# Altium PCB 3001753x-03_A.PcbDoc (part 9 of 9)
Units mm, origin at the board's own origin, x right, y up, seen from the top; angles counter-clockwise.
Board outline 210 x 130 mm, 8 copper layers (1-TOP, 2-GND, 3-INTOP, 4-PWR, 5-PWR, 6-INBOT, 7-GND, 8-BOTTOM), stack 1.646 mm thick; 676 components, 623 nets, 2861 pads, 2382 vias.
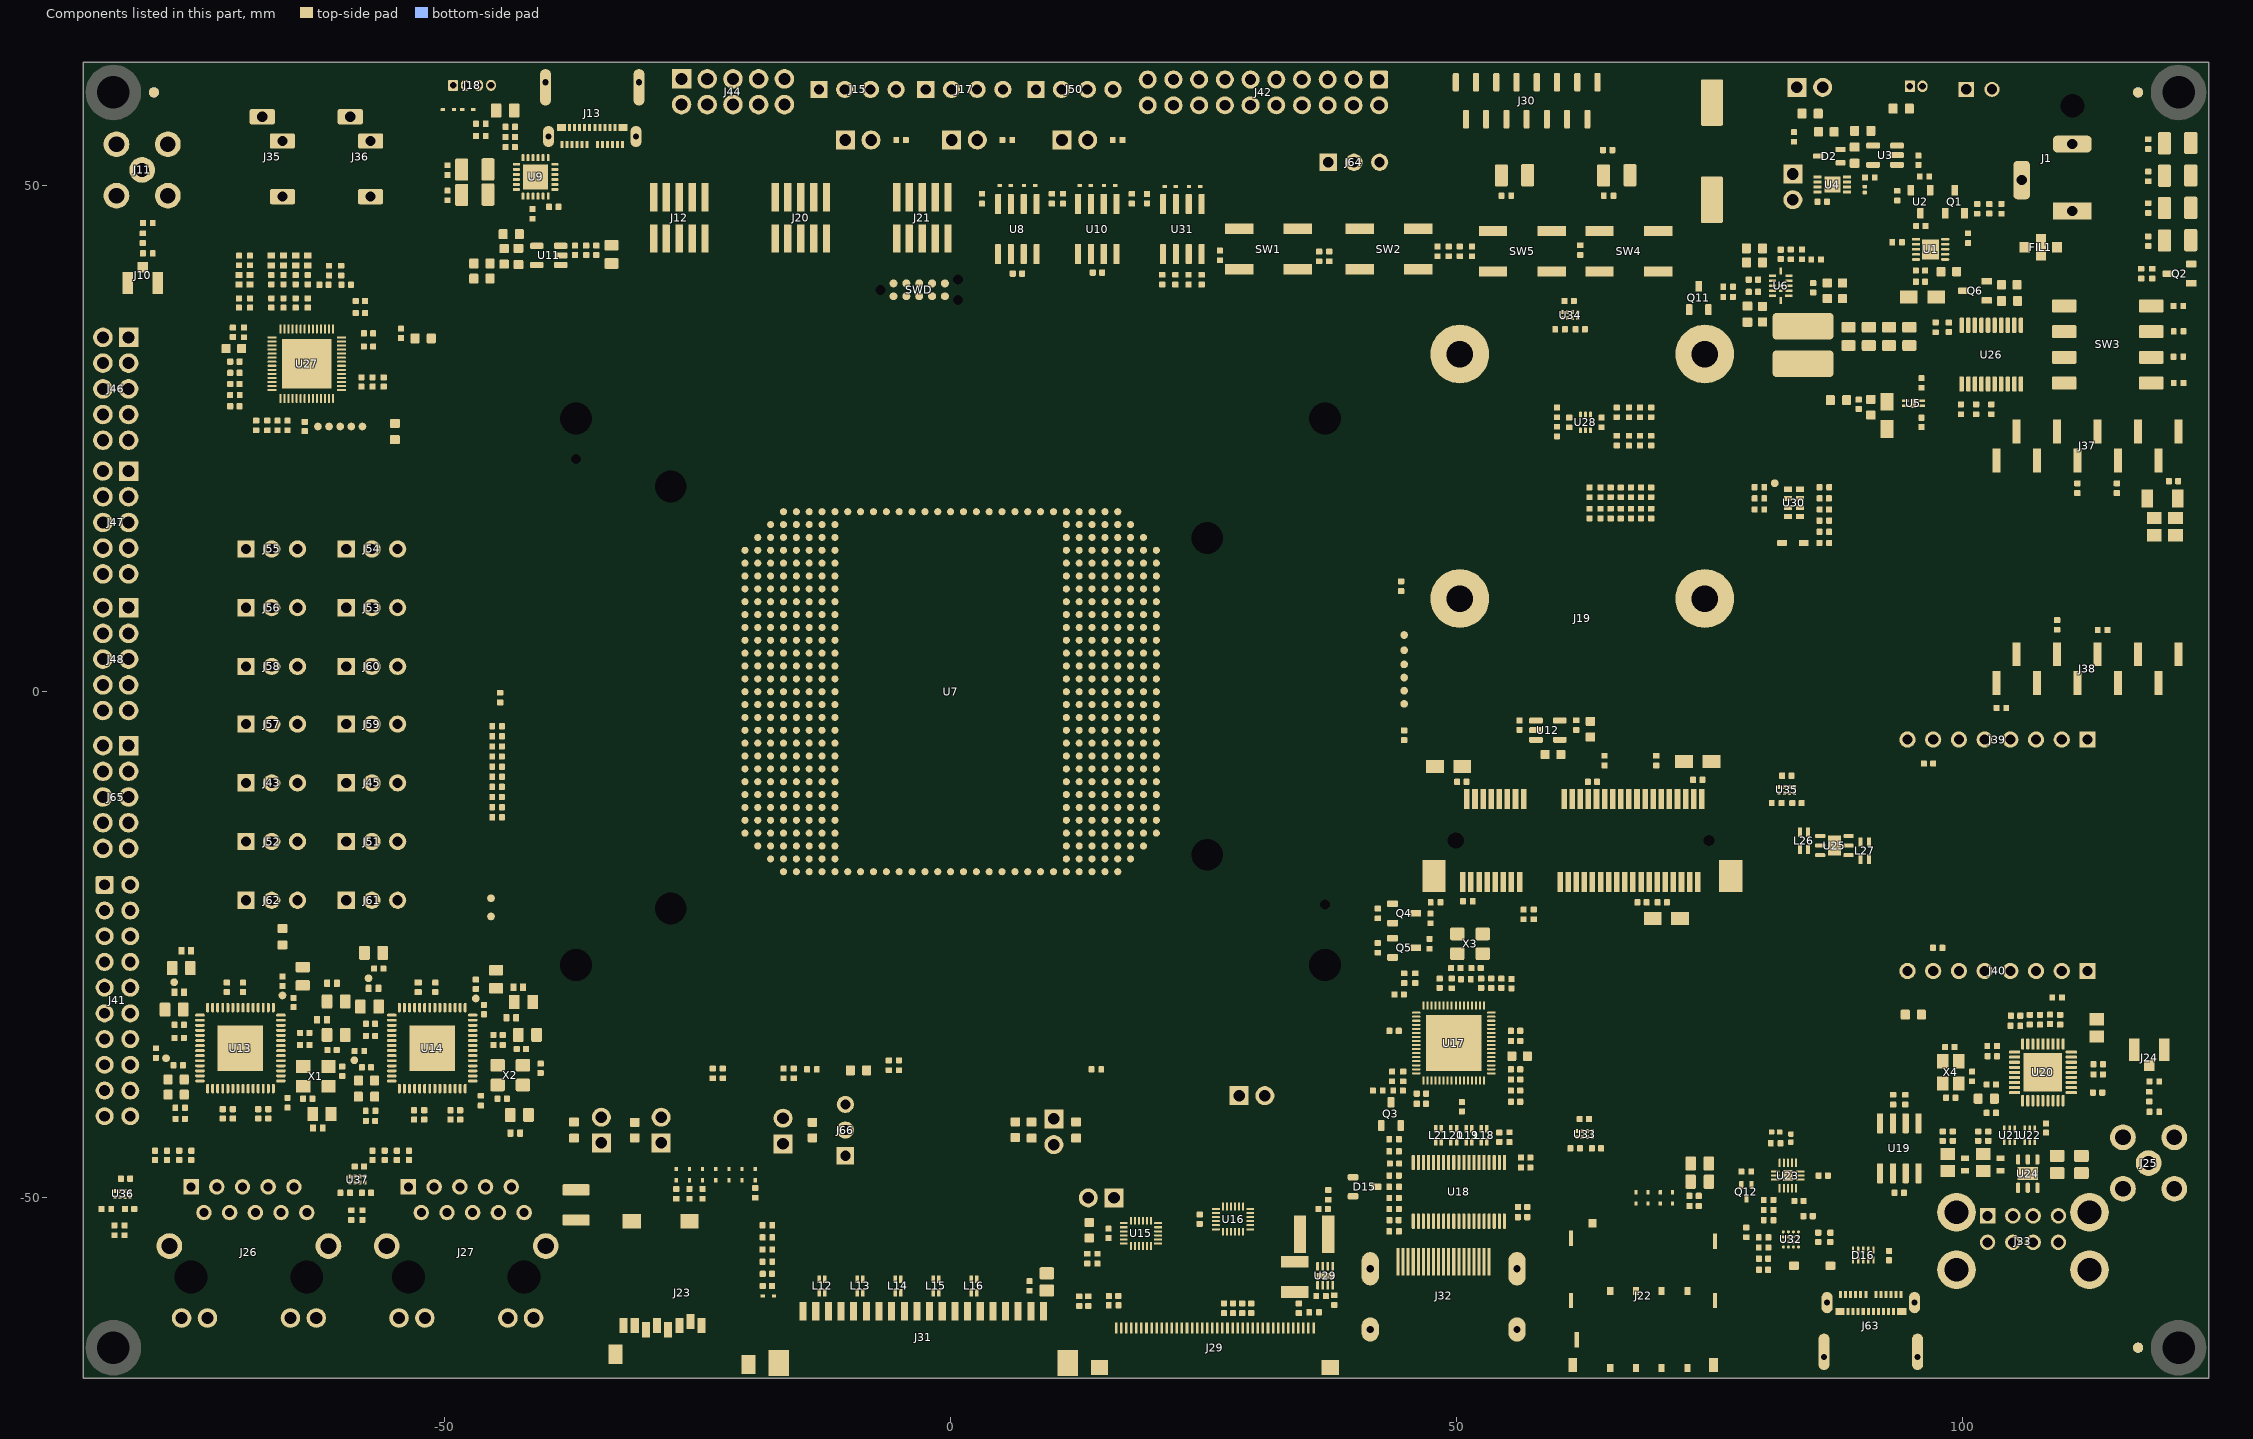
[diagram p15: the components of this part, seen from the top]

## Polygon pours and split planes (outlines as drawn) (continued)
3V3_ETH1 on 5-PWR (split plane): -59.451,-44.337 -61.563,-46.449 -77.2,-46.449 -77.239,-46.454 -77.276,-46.469 -77.307,-46.493 -80.707,-49.893 -80.731,-49.924 -80.746,-49.961 -80.751,-50 -80.751,-52.037 -81.363,-52.649 -82.837,-52.649 -83.149,-52.337 -83.149,-47.563 -79.193,-43.607 -79.169,-43.576 -79.154,-43.539 -79.149,-43.5 -79.149,-41.6 -79.149,-26.463 -76.837,-24.151 -59.451,-24.151
3V3_ETH2 on 5-PWR (split plane): -33.151,-33.163 -33.151,-42.437 -33.863,-43.149 -38.7,-43.149 -38.739,-43.154 -38.776,-43.169 -38.807,-43.193 -39.707,-44.093 -39.731,-44.124 -39.746,-44.161 -39.751,-44.2 -39.751,-46.537 -39.763,-46.549 -53.5,-46.549 -53.539,-46.554 -53.576,-46.569 -53.607,-46.593 -57.913,-50.899 -59.187,-50.899 -59.649,-50.437 -59.649,-48.3 -59.654,-48.261 -59.663,-48.239 -59.669,-48.224 -59.693,-48.193 -61.286,-46.6 -59.193,-44.507 -59.169,-44.476 -59.154,-44.439 -59.149,-44.4 -59.149,-24.251 -42.063,-24.251
1V8_SOM_EXT on 5-PWR (split plane): 270 vertices, not listed, extent -85.198,-67.298 87.449,57.249
NetC72_2 on 5-PWR (split plane): -64.551,-33.763 -64.551,-38.437 -67.063,-40.949 -73.237,-40.949 -75.749,-38.437 -75.749,-35.5 -75.749,-33.263 -74.937,-32.451 -65.863,-32.451
NetC99_2 on 5-PWR (split plane): -45.451,-33.763 -45.451,-38.237 -48.363,-41.149 -54.537,-41.149 -57.049,-38.637 -57.049,-35.7 -57.049,-33.063 -56.237,-32.251 -46.963,-32.251
VCC_MCA on 5-PWR (split plane): 84.749,61.698 84.749,57 84.749,55.5 84.754,55.461 84.769,55.424 84.793,55.393 86.693,53.493 86.724,53.469 86.761,53.454 86.8,53.449 87.637,53.449 89.649,51.437 89.649,48.463 88.693,47.507 82.537,41.351 24,41.351 23.961,41.346 23.924,41.331 23.893,41.307 21.293,38.707 21.269,38.676 21.263,38.661 21.254,38.639 21.249,38.6 21.249,7.493 20.892,7.136 19.748,7.136 18.566,8.318 18.566,35.2 18.561,35.239 18.546,35.276 18.522,35.307 18.491,35.331 18.477,35.336 16.607,37.207 16.576,37.231 16.539,37.246 16.5,37.251 -20.137,37.251 -21.149,38.263 -21.149,41.037 -20.037,42.149 -10.3,42.149 -10.261,42.154 -10.239,42.163 -10.224,42.169 -10.193,42.193 -9.093,43.293 -9.069,43.324 -9.054,43.361 -9.049,43.4 -9.049,48.8 -9.054,48.839 -9.069,48.876 -9.093,48.907 -9.593,49.407 -9.624,49.431 -9.661,49.446 -9.7,49.451 -21.037,49.451 -23.793,52.207 -29.093,57.507 -29.124,57.531 -29.161,57.546 -29.2,57.551 -74,57.551 -74.039,57.546 -74.061,57.537 -74.076,57.531 -74.107,57.507 -77.407,54.207 -77.431,54.176 -77.446,54.139 -77.451,54.1 -77.451,16.363 -79.463,14.351 -85.198,14.351 -85.198,61.698
USBC_VBUS on 5-PWR (split plane): 95.371,-55.554 95.371,-67.298 86.41,-67.298 86.41,-59.78 86.4,-59.731 86.372,-59.689 85.029,-58.346 85.029,-55.254 85.954,-54.329 94.146,-54.329
5V on 5-PWR (split plane): 87.449,-22.8 87.454,-22.839 87.469,-22.876 87.493,-22.907 88.193,-23.607 88.224,-23.631 88.261,-23.646 88.3,-23.651 97.337,-23.651 97.649,-23.963 97.649,-25.537 97.337,-25.849 88.1,-25.849 88.061,-25.854 88.039,-25.863 88.024,-25.869 87.993,-25.893 87.643,-26.243 87.642,-26.245 87.64,-26.246 64.142,-51.095 56.687,-58.549 9.663,-58.549 8.651,-57.537 8.651,-55.463 11.563,-52.551 20.425,-52.551 20.464,-52.546 20.486,-52.537 20.501,-52.531 20.532,-52.507 23.388,-49.651 35.575,-49.651 35.614,-49.646 35.636,-49.637 35.651,-49.631 35.682,-49.607 37.238,-48.051 51.7,-48.051 51.739,-48.046 51.761,-48.037 51.776,-48.031 51.807,-48.007 82.607,-17.207 82.631,-17.176 82.646,-17.139 82.651,-17.1 82.651,29.037 84.063,30.449 87.449,30.449
VIN_PROT on 5-PWR (split plane): 123.798,61.698 123.798,-67.298 95.629,-67.298 95.629,-55.5 95.62,-55.45 95.592,-55.408 94.292,-54.108 94.25,-54.08 94.2,-54.071 85.9,-54.071 85.85,-54.08 85.808,-54.108 84.808,-55.108 84.78,-55.15 84.771,-55.2 84.771,-58.4 84.78,-58.45 84.808,-58.492 86.151,-59.834 86.151,-67.298 3.451,-67.298 3.451,-43.851 8.9,-43.851 8.939,-43.846 8.976,-43.831 9.007,-43.807 9.031,-43.776 9.046,-43.739 9.051,-43.7 9.051,-41.263 10.5,-39.814 11.949,-41.263 11.949,-50.437 11.493,-50.893 11.469,-50.924 11.454,-50.961 11.449,-51 11.449,-52.259 11.424,-52.269 11.393,-52.293 8.393,-55.293 8.369,-55.324 8.354,-55.361 8.349,-55.4 8.349,-57.6 8.354,-57.639 8.369,-57.676 8.393,-57.707 9.493,-58.807 9.524,-58.831 9.561,-58.846 9.6,-58.851 56.75,-58.851 56.789,-58.846 56.826,-58.831 56.857,-58.807 64.357,-51.307 64.358,-51.305 64.36,-51.304 87.858,-26.455 88.163,-26.151 97.4,-26.151 97.439,-26.146 97.476,-26.131 97.507,-26.107 97.907,-25.707 97.931,-25.676 97.946,-25.639 97.951,-25.6 97.951,-23.9 97.946,-23.861 97.931,-23.824 97.907,-23.793 97.507,-23.393 97.476,-23.369 97.439,-23.354 97.4,-23.349 88.363,-23.349 87.751,-22.737 87.751,30.6 87.751,36.2 87.746,36.239 87.731,36.276 87.707,36.307 82.814,41.2 88.907,47.293 89.907,48.293 89.931,48.324 89.946,48.361 89.951,48.4 89.951,51.5 89.946,51.539 89.931,51.576 89.907,51.607 87.807,53.707 87.776,53.731 87.739,53.746 87.7,53.751 86.863,53.751 85.051,55.563 85.051,57 85.051,61.698
5V_DBG on 5-PWR (split plane): -31.251,57.237 -31.251,44.963 -32.163,44.051 -38.337,44.051 -39.569,45.283 -39.569,57.249 -31.263,57.249
VSYS2 on 5-PWR (split plane): 17.649,-26.237 17.37,-26.516 7.093,-36.793 7.069,-36.824 7.063,-36.839 7.054,-36.861 7.049,-36.9 7.049,-43.549 3.451,-43.549 3.451,-30.863 15.307,-19.007 15.331,-18.976 15.346,-18.939 15.351,-18.9 15.351,-14.663 15.963,-14.051 17.649,-14.051
VSYS on 5-PWR (split plane): 21.749,-10.363 21.749,-28.1 21.749,-28.137 10.393,-39.493 8.793,-41.093 8.769,-41.124 8.754,-41.161 8.749,-41.2 8.749,-43.549 7.351,-43.549 7.351,-36.963 17.584,-26.73 17.907,-26.407 17.931,-26.376 17.946,-26.339 17.951,-26.3 17.951,-9.063 18.063,-8.951 20.337,-8.951
1V8_PHY_1 on 4-PWR (split plane): -75.407,-24.807 -74.551,-25.663 -74.551,-27.5 -74.546,-27.539 -74.537,-27.561 -74.531,-27.576 -74.507,-27.607 -73.907,-28.207 -73.876,-28.231 -73.839,-28.246 -73.8,-28.251 -64.263,-28.251 -63.507,-29.007 -62.751,-29.763 -62.751,-36.1 -62.751,-39.437 -63.763,-40.449 -74,-40.449 -74.039,-40.454 -74.065,-40.465 -74.076,-40.469 -74.107,-40.493 -75.107,-41.493 -81.663,-48.049 -81.837,-48.049 -82.349,-47.537 -82.349,-47.363 -79.093,-44.107 -79.069,-44.076 -79.063,-44.061 -79.054,-44.039 -79.049,-44 -79.049,-40.4 -79.049,-39.7 -79.049,-28.7 -79.049,-26.263 -77.237,-24.451 -75.763,-24.451
3V3_SOM_EXT on 4-PWR (split plane): 198 vertices, not listed, extent -85.198,-67.298 123.798,61.698
3V3 on 4-PWR (split plane): -31.251,61.698 -31.251,42.6 -31.246,42.561 -31.237,42.539 -31.231,42.524 -31.207,42.493 -25.607,36.893 -18.607,29.893 -18.576,29.869 -18.539,29.854 -18.5,29.849 39.2,29.849 39.239,29.854 39.276,29.869 39.307,29.893 46.263,36.849 49.337,36.849 50.149,36.037 50.149,9.263 34.093,-6.793 34.069,-6.824 34.054,-6.861 34.049,-6.9 34.049,-22.137 13.037,-43.149 -2.2,-43.149 -6.049,-43.149 -6.049,-38.563 0.463,-32.051 3.8,-32.051 3.839,-32.046 3.876,-32.031 3.907,-32.007 15.407,-20.507 15.431,-20.476 15.437,-20.461 15.446,-20.439 15.451,-20.4 15.451,-15.6 15.446,-15.561 15.431,-15.524 15.407,-15.493 15.007,-15.093 14.976,-15.069 14.961,-15.063 14.939,-15.054 14.9,-15.049 13.2,-15.049 13.161,-15.054 13.139,-15.063 13.124,-15.069 13.093,-15.093 12.593,-15.593 12.569,-15.624 12.563,-15.639 12.554,-15.661 12.549,-15.7 12.549,-18.637 6.237,-24.949 -3.9,-24.949 -3.939,-24.954 -3.976,-24.969 -4.007,-24.993 -18.307,-39.293 -18.331,-39.324 -18.346,-39.361 -18.351,-39.4 -18.351,-43.149 -32.537,-43.149 -32.849,-42.837 -32.849,-42 -32.849,-27.5 -32.854,-27.461 -32.869,-27.424 -32.893,-27.393 -36.349,-23.937 -36.349,28.5 -36.354,28.539 -36.369,28.576 -36.393,28.607 -46.249,38.463 -46.249,39 -46.249,40.137 -40.893,45.493 -40.869,45.524 -40.854,45.561 -40.849,45.6 -40.849,55.7 -40.854,55.739 -40.869,55.776 -40.893,55.807 -41.893,56.807 -41.924,56.831 -41.939,56.837 -41.961,56.846 -42,56.851 -43.7,56.851 -43.739,56.846 -43.776,56.831 -43.807,56.807 -44.663,55.951 -72.9,55.951 -72.939,55.946 -72.976,55.931 -73.007,55.907 -75.207,53.707 -75.231,53.676 -75.237,53.661 -75.246,53.639 -75.251,53.6 -75.251,-4.137 -77.563,-6.449 -85.198,-6.449 -85.198,61.698
3V3_CODEC on 4-PWR (split plane): -52.751,30.037 -52.751,26.563 -53.363,25.951 -68.737,25.951 -70.249,27.463 -70.249,28.5 -70.249,31.437 -69.537,32.149 -54.863,32.149
1V8_PHY_2 on 4-PWR (split plane): -44.557,-29.007 -43.551,-30.013 -43.551,-35.85 -43.551,-39.187 -44.913,-40.549 -53.5,-40.549 -53.539,-40.554 -53.576,-40.569 -53.607,-40.593 -55.963,-42.949 -58.537,-42.949 -59.949,-41.537 -59.949,-40 -59.949,-30.513 -58.443,-29.007 -57.087,-27.651 -45.913,-27.651
3V3_DBG on 4-PWR (split plane): -41.151,55.637 -41.151,45.663 -46.507,40.307 -46.531,40.276 -46.546,40.239 -46.551,40.2 -46.551,39.151 -50.249,39.151 -50.249,55.649 -44.6,55.649 -44.561,55.654 -44.524,55.669 -44.493,55.693 -43.637,56.549 -42.063,56.549
1V8 on 4-PWR (split plane): 15.149,-15.663 15.149,-20.337 3.737,-31.749 0.4,-31.749 0.361,-31.754 0.339,-31.763 0.324,-31.769 0.293,-31.793 -6.307,-38.393 -6.331,-38.424 -6.346,-38.461 -6.351,-38.5 -6.351,-43.149 -18.049,-43.149 -18.049,-39.463 -3.837,-25.251 6.3,-25.251 6.339,-25.246 6.361,-25.237 6.376,-25.231 6.407,-25.207 12.807,-18.807 12.831,-18.776 12.837,-18.761 12.846,-18.739 12.851,-18.7 12.851,-15.763 13.263,-15.351 14.837,-15.351
5V_OUT_HDMI on 4-PWR (split plane): 56.349,-49.863 56.349,-54.837 55.437,-55.749 43.163,-55.749 42.151,-54.737 42.151,-49.563 42.663,-49.051 55.537,-49.051
NetC148_2 on 4-PWR (split plane): 115.349,-33.963 115.349,-40.537 113.637,-42.249 105.563,-42.249 103.551,-40.237 103.551,-36.063 104.063,-35.551 106,-35.551 106.039,-35.546 106.061,-35.537 106.076,-35.531 106.107,-35.507 106.507,-35.107 106.531,-35.076 106.535,-35.065 106.546,-35.039 106.551,-35 106.551,-34.063 107.363,-33.251 114.637,-33.251
VIN on 4-PWR (split plane): 105.549,43.377 105.549,41.763 105.337,41.551 101.363,41.551 98.507,44.407 98.476,44.431 98.439,44.446 98.4,44.451 92.863,44.451 91.851,45.463 91.851,51.537 92.163,51.849 97.077,51.849
5V on 4-PWR (split plane): 6.549,61.698 6.549,50.9 6.554,50.861 6.569,50.824 6.593,50.793 10.243,47.143 10.893,46.493 10.924,46.469 10.935,46.465 10.961,46.454 11,46.449 18.437,46.449 19.149,45.737 19.149,40.1 19.154,40.061 19.169,40.024 19.193,39.993 19.593,39.593 19.624,39.569 19.661,39.554 19.7,39.549 20.4,39.549 20.439,39.554 20.476,39.569 20.507,39.593 20.907,39.993 20.931,40.024 20.946,40.061 20.951,40.1 20.951,45.737 21.663,46.449 75.737,46.449 76.649,45.537 76.649,43 76.649,42.7 76.649,41.2 76.654,41.161 76.663,41.139 76.669,41.124 76.693,41.093 87.449,30.337 87.449,26.651 81.413,26.651 71.857,36.207 71.826,36.231 71.811,36.237 71.789,36.246 71.75,36.251 50.363,36.251 49.507,37.107 49.476,37.131 49.439,37.146 49.4,37.151 46.2,37.151 46.161,37.146 46.124,37.131 46.093,37.107 39.137,30.151 -18.437,30.151 -25.393,37.107 -30.949,42.663 -30.949,61.698
3V3_USB on 4-PWR (split plane): 115.449,-30.563 115.449,-32.137 114.637,-32.949 107.3,-32.949 107.261,-32.954 107.235,-32.965 107.224,-32.969 107.193,-32.993 106.293,-33.893 106.269,-33.924 106.263,-33.939 106.254,-33.961 106.249,-34 106.249,-34.937 105.937,-35.249 104,-35.249 103.961,-35.254 103.939,-35.263 103.924,-35.269 103.893,-35.293 103.293,-35.893 103.269,-35.924 103.254,-35.961 103.249,-36 103.249,-40.149 92.263,-40.149 91.951,-39.837 91.951,-37.963 95.207,-34.707 95.231,-34.676 95.246,-34.639 95.251,-34.6 95.251,-30.463 95.763,-29.951 114.837,-29.951
3V3_BOARD on 4-PWR (split plane): 87.193,34.193 87.224,34.169 87.261,34.154 87.3,34.149 94.737,34.149 95.749,33.137 95.749,25.8 95.749,17.8 95.754,17.761 95.763,17.739 95.769,17.724 95.793,17.693 96.793,16.693 96.824,16.669 96.861,16.654 96.9,16.649 113.837,16.649 114.449,16.037 114.449,14.363 113.737,13.651 97,13.651 96.961,13.646 96.924,13.631 96.893,13.607 95.793,12.507 95.769,12.476 95.754,12.439 95.749,12.4 95.749,2.863 91.893,-0.993 91.869,-1.024 91.863,-1.039 91.854,-1.061 91.849,-1.1 91.849,-5.737 73.337,-24.249 54.663,-24.249 50.551,-20.137 50.551,-5.963 54.363,-2.151 78,-2.151 78.039,-2.146 78.076,-2.131 78.107,-2.107 87.707,7.493 87.731,7.524 87.746,7.561 87.751,7.6 87.751,30.4 87.746,30.439 87.735,30.465 87.731,30.476 87.707,30.507 76.951,41.263 76.951,42.849 78.537,42.849
GND on 7-GND (split plane): 123.798,61.698 123.798,-67.298 -38.3,-67.298 -38.3,-52.7 -57.7,-52.7 -57.7,-67.298 -59.7,-67.298 -59.7,-52.7 -79.28,-52.7 -79.28,-67.298 -85.198,-67.298 -85.198,61.698
GND on 2-GND (split plane): 123.798,61.698 123.798,-67.298 -38.3,-67.298 -38.3,-52.7 -57.7,-52.7 -57.7,-67.298 -59.8,-67.298 -59.8,-52.7 -79.28,-52.7 -79.28,-67.298 -85.198,-67.298 -85.198,61.698

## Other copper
1-TOP:
  rectangle net 3V3_BOARD: 86.8,31.3 87.8,33.4
  region net GND: 96,45 97.6,45 97.6,42.4 96.1,42.4 96,42.5
  pour cut-out: 38.15,-53.8 38.15,-67.8 59.15,-67.8 59.15,-53.8
  pour cut-out: -21.7,-14.6 -16.7,-19.6 17.3,-19.6 21.3,-15.6 21.3,14.4 17.3,18.4 -16.7,18.4 -21.7,13.4
  region net CT2: -54.245,-47.752 -54.245,-48.752 -52.845,-48.752 -52.845,-47.752
  region net CT1: -75.715,-47.752 -75.715,-48.752 -74.315,-48.752 -74.315,-47.752
  pour cut-out: 84.9,-58.6 84.9,-67.8 96.9,-67.8 96.9,-58.6
  pour cut-out: -54.9,-47.8 -57.7,-50.6 -57.7,-67.8 -38.3,-67.8 -38.3,-53.3 -42.8,-53.3 -42.8,-47.8
  pour cut-out: -76.3,-47.8 -79.3,-50.8 -79.3,-67.8 -59.8,-67.8 -59.8,-53.2 -64.3,-53.2 -64.3,-47.8
  pour cut-out: 97.1,-49.9 97.1,-67.8 114.8,-67.8 114.8,-50 113.6,-48.8 98.2,-48.8
  region net NetL1_1: 84.6,39.5 84.6,36.6 83.4,36.6 83.4,39.3 83.2,39.5 82,39.5 82,39.7 83.2,39.7 83.3,39.8 84.3,39.8
  text "30017532-03_TOP" at 63.3,-28.95 h1.5
3-INTOP:
  pour cut-out: -76.3,-47.8 -79.3,-50.8 -79.3,-67.8 -59.8,-67.8 -59.8,-53.2 -64.3,-53.2 -64.3,-47.8
  pour cut-out: -54.9,-47.8 -57.7,-50.6 -57.7,-67.8 -38.3,-67.8 -38.3,-53.3 -42.8,-53.3 -42.8,-47.8
6-INBOT:
  pour cut-out: -76.3,-47.8 -79.3,-50.8 -79.3,-67.8 -59.8,-67.8 -59.8,-53.2 -64.3,-53.2 -64.3,-47.8
  pour cut-out: -54.9,-47.8 -57.7,-50.6 -57.7,-67.8 -38.3,-67.8 -38.3,-53.3 -42.8,-53.3 -42.8,-47.8
8-BOTTOM:
  pour cut-out: -76.3,-47.8 -79.3,-50.8 -79.3,-67.8 -59.8,-67.8 -59.8,-53.2 -64.3,-53.2 -64.3,-47.8
  pour cut-out: -54.9,-47.8 -57.7,-50.6 -57.7,-67.8 -38.3,-67.8 -38.3,-53.3 -42.8,-53.3 -42.8,-47.8
  text "30017532-03_BOT" at 85.1,-28.95 h1.5
2-GND (plane layer: these items are gaps in the copper):
  region: -57.7,-67.7 -57.7,-52.7 -38.3,-52.7 -38.3,-67.7
  region: -79.28,-67.8 -79.28,-52.7 -59.8,-52.7 -59.8,-67.8
4-PWR (plane layer: these items are gaps in the copper):
  region: -79.28,-67.8 -79.28,-50.78 -76.3,-47.8 -64.3,-47.8 -64.3,-53.2 -59.8,-53.2 -59.8,-67.8
  region: -57.7,-67.7 -57.7,-51 -54.5,-47.8 -42.8,-47.8 -42.8,-53.3 -38.3,-53.3 -38.3,-67.7
  lines w0.3: -85.7,-6.6 -77.5,-6.6 -75.1,-4.2 -75.1,53.6 -72.9,55.8 -50.4,55.8 ; -75,-41.6 -74,-40.6 ; -44,62.2 -31.1,62.2 -31.1,42.6 -25.5,37 -18.5,30 39.2,30 46.2,37 49.4,37 50.3,36.1 ; -18.4,-43.3 -10.4,-43.3 ; -18.2,-43.3 -18.2,-39.4 -3.9,-25.1 6.3,-25.1 12.7,-18.7 12.7,-15.7 13.2,-15.2 14.9,-15.2 15.3,-15.6 15.3,-20.4 3.8,-31.9 0.4,-31.9 -6.2,-38.5 -6.2,-43.3 ; 6.7,62.3 6.7,50.9 10.35,47.25 11,46.6 18.5,46.6 19.3,45.8 19.3,40.1 19.7,39.7 20.4,39.7 20.8,40.1 20.8,45.8 21.6,46.6 75.8,46.6 76.8,45.6 76.8,41.2 87.6,30.4 87.6,7.6 78,-2 54.3,-2 50.4,-5.9 50.4,-20.2 54.6,-24.4 73.4,-24.4 92,-5.8 92,-1.1 95.9,2.8 95.9,12.4 97,13.5 98.1,13.5 113.8,13.5 114.6,14.3 114.6,16.1 113.9,16.8 96.9,16.8 95.9,17.8 95.9,25.8 95.9,33.2 94.8,34.3 87.3,34.3 78.6,43 ; 76.8,42.7 76.8,43 78.6,43 ; 78.4,43 78.6,43 ; 87.6,26.5 81.35,26.5 71.75,36.1 50.3,36.1 ; 93.2,44.3 92.8,44.3 ; -74,-40.6 -81.6,-48.2 -81.9,-48.2 -82.5,-47.6 -82.5,-47.3 -79.2,-44 -79.2,-40.4 -79.2,-39.7 -79.2,-28.7 -79.2,-26.2 -77.3,-24.3 -75.7,-24.3 -75.3,-24.7 -74.4,-25.6 -74.4,-27.5 -73.8,-28.1 -64.2,-28.1 -63.4,-28.9 -62.6,-29.7 -62.6,-36.1 -62.6,-39.5 -63.7,-40.6 -74,-40.6 ; -50.4,39 -50.4,55.8 ; -50.4,39 -46.4,39 ; -50.4,39 -50.4,55.8 ; -50.4,55.8 -44.6,55.8 -43.7,56.7 -42,56.7 -41,55.7 -41,45.6 -46.4,40.2 -46.4,39 ; -46.4,39 -46.4,38.4 -36.5,28.5 -36.5,-24 -33,-27.5 -33,-42 -33,-42.9 -32.6,-43.3 -2.2,-43.3 13.1,-43.3 34.2,-22.2 34.2,-6.9 50.3,9.2 50.3,36.1 ; 92.8,44.3 91.7,45.4 91.7,51.6 92.1,52 97.14,52 105.7,43.44 105.7,41.7 105.4,41.4 101.3,41.4 98.4,44.3 94.8,44.3 92.8,44.3 ; 103.4,-40.3 92.2,-40.3 91.8,-39.9 91.8,-37.9 95.1,-34.6 95.1,-30.4 95.7,-29.8 114.9,-29.8 115.6,-30.5 115.6,-32.2 114.7,-33.1 ; 103.4,-40.3 103.4,-36 104,-35.4 106,-35.4 106.4,-35 106.4,-34 107.3,-33.1 114.7,-33.1 ; 103.4,-40.3 105.5,-42.4 113.7,-42.4 115.5,-40.6 115.5,-33.9 114.7,-33.1 ; -70.4,27.4 -68.8,25.8 -53.3,25.8 -52.6,26.5 -52.6,30.1 -54.8,32.3 -69.6,32.3 -70.4,31.5 -70.4,28.5 -70.4,27.4 ; -60.1,-41.6 -60.1,-40 -60.1,-30.45 -58.55,-28.9 -57.15,-27.5 -45.85,-27.5 -44.45,-28.9 -43.4,-29.95 -43.4,-35.85 -43.4,-39.25 -44.85,-40.7 -53.5,-40.7 -55.9,-43.1 -58.6,-43.1 -60.1,-41.6 ; 42,-54.8 43.1,-55.9 55.5,-55.9 56.5,-54.9 56.5,-49.8 55.6,-48.9 42.6,-48.9 42,-49.5 42,-54.8
5-PWR (plane layer: these items are gaps in the copper):
  region: -79.28,-67.8 -79.28,-50.78 -76.3,-47.8 -64.3,-47.8 -64.3,-53.2 -59.8,-53.2 -59.8,-67.8
  region: -57.7,-67.7 -57.7,-51 -54.5,-47.8 -42.8,-47.8 -42.8,-53.3 -38.3,-53.3 -38.3,-67.7
  lines w0.254: 84.1,-67.9 86.28,-67.9 86.28,-59.78 84.9,-58.4 84.9,-55.2 85.9,-54.2 94.2,-54.2 95.5,-55.5 95.5,-67.8
  lines w0.3: -85.7,14.2 -79.4,14.2 -77.3,16.3 -77.3,54.1 -74,57.4 -29.2,57.4 -23.9,52.1 -21.1,49.3 -9.7,49.3 -9.2,48.8 -9.2,43.4 -10.3,42.3 -20.1,42.3 -21.3,41.1 -21.3,38.2 -20.2,37.1 16.5,37.1 18.4,35.2 ; -59.3,-24.1 -42,-24.1 -33,-33.1 -33,-42.5 -33.8,-43.3 -38.7,-43.3 -39.6,-44.2 -39.6,-46.6 -39.7,-46.7 -53.5,-46.7 -57.85,-51.05 -59.25,-51.05 -59.8,-50.5 -59.8,-48.3 -61.5,-46.6 ; -39.72,57.4 -39.72,45.22 -38.4,43.9 -32.1,43.9 -31.1,44.9 -31.1,57.3 -31.2,57.4 ; 5.3,-43.7 6.3,-43.7 ; 11.6,-52.3 11.6,-51 12.1,-50.5 12.1,-41.2 10.5,-39.6 ; 17.8,-13.9 15.9,-13.9 15.2,-14.6 15.2,-18.9 3.3,-30.8 3.3,-43.7 ; 18.415,35.2 18.415,8.255 19.685,6.985 20.955,6.985 21.4,7.43 21.4,38.6 24,41.2 82.6,41.2 ; 84.9,62.2 84.9,57 84.9,55.5 86.8,53.6 87.7,53.6 89.8,51.5 89.8,48.4 88.8,47.4 82.6,41.2 ; 87.6,30.6 84,30.6 82.5,29.1 82.5,-17.1 51.7,-47.9 37.175,-47.9 35.575,-49.5 23.325,-49.5 20.425,-52.4 11.5,-52.4 8.5,-55.4 8.5,-57.6 9.6,-58.7 56.75,-58.7 64.25,-51.2 87.75,-26.35 88.1,-26 92.25,-26 97.4,-26 97.8,-25.6 97.8,-23.9 97.4,-23.5 88.3,-23.5 87.6,-22.8 87.6,36.2 82.6,41.2 ; -61.5,-46.6 -75.1,-46.6 -77.2,-46.6 -80.6,-50 -80.6,-52.1 -81.3,-52.8 -82.9,-52.8 -83.3,-52.4 -83.3,-47.5 -79.3,-43.5 -79.3,-41.6 -79.3,-26.4 -76.9,-24 -59.3,-24 -59.3,-44.4 -61.5,-46.6 ; 3.3,-67.8 3.3,-67.8 ; 3.3,-67.8 3.3,-43.7 ; 3.3,-43.7 7.2,-43.7 ; 7.2,-43.7 8.9,-43.7 8.9,-41.2 10.5,-39.6 ; 7.2,-43.7 7.2,-36.9 17.477,-26.623 17.8,-26.3 17.8,-9 18,-8.8 20.4,-8.8 21.9,-10.3 21.9,-28.1 21.9,-28.2 10.5,-39.6 ; -75.9,-38.5 -75.9,-35.5 -75.9,-33.2 -75,-32.3 -65.8,-32.3 -64.4,-33.7 -64.4,-38.5 -67,-41.1 -72.2,-41.1 -73.3,-41.1 -75.9,-38.5 ; -57.2,-38.7 -54.6,-41.3 -53.5,-41.3 -48.3,-41.3 -45.3,-38.3 -45.3,-33.7 -46.9,-32.1 -56.3,-32.1 -57.2,-33 -57.2,-35.7 -57.2,-38.7
7-GND (plane layer: these items are gaps in the copper):
  region: -79.28,-67.8 -79.28,-52.7 -59.7,-52.7 -59.7,-67.8
  region: -57.7,-67.7 -57.7,-52.7 -38.3,-52.7 -38.3,-67.7

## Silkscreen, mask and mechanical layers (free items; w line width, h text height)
Top Overlay:
  drawing of 78 lines, arcs and shapes, not listed
  text "COIN-CELL" at 91.9,55.4 h1
  text "MIPI Camera" at 50.302,52.6 h1.2
  text "CAN1" at -10.8,52.2 h1
  text "CAN2" at -0.2,52.2 h1
  text "RS485" at 10.1,52.1 h1
  text "VIN" at 102.05,51.4 h1
  text "5V" at 102.067,49.9 h1
  text "CONSOLE" at -38.099,49.2 h1.2
  text "HEADPHONE" at -54.765,44.35 h1.1
  text "MIC" at -75.7,44.3 h1.2
  text "JTAG" at -17.3,41.3 h1.5
  text "POWER" at 28.301,38.9 h1.2
  text "RESET" at 40.201,38.9 h1.2
  text "USER2" at 53.401,38.9 h1.2
  text "USER1" at 64.101,38.9 h1.2
  text "I2C4" at 61.051,28 h1
  text "I2C3" at 64.251,21.2 h1
  text "Right: Alternate" at -62.05,16.283 h1
  text "Left: ENET2" at -74.85,16.25 h1
  text "XBEE" at 108.1,12.9 h1
  text "GND" at 94,-6.8 h1 r270
  text "MOSI" at 99.1,-6.8 h1 r270
  text "MISO" at 101.7,-6.8 h1 r270
  text "SCK" at 104.2,-6.8 h1 r270
  text "CS" at 106.7,-6.8 h1 r270
  text "RST" at 109.3,-6.8 h1 r270
  text "AN" at 111.8,-6.8 h1 r270
  text "+3V3" at 96.7,-7.7 h1 r270
  text "mikro" at 116.65,-16.35 h1 r270
  text "BUS" at 114.77,-16.46 h1.5 r270
  text "Right: MIKROBUS UART" at -64.85,-18.817 h1
  text "Left: RS485" at -76.55,-18.85 h1
  text "+5V" at 96.7,-21.8 h1 r270
  text "GND" at 94,-23.1 h1 r270
  text "SDA" at 99.2,-23.1 h1 r270
  text "SCL" at 101.7,-23.1 h1 r270
  text "PWM" at 111.9,-23.1 h1 r270
  text "INT" at 109.3,-23.267 h1 r270
  text "TX" at 104.2,-24.1 h1 r270
  text "RX" at 106.8,-24.1 h1 r270
  text "ENET1" at -72.399,-46.4 h1.2
  text "ENET2" at -50.899,-46.4 h1.2
  text "SIM" at 61.1,-51.4 h1.2
  text "HDMI" at 38.301,-54.5 h1.2
  text "LVDS Display" at -8.498,-57.2 h1.2
  text "MIPI Display" at 18.602,-59.5 h1.2
  text "MICRO SD" at -34.4,-63.599 h1.2 r90
  text "USB OTG" at 76.701,-65.6 h1.2
Bottom Overlay:
  drawing of 143 lines, arcs and shapes, not listed
  text "J44" at -18.634,54.6 h2
  text "J42" at 33.566,54.2 h2
  text "J64" at 50.1,51.3 h2.05
  text "POWER_BUTTON" at 59.2,49 h0.82
  text "1" at 47.6,48.8 h0.82
  text "RSET_BUTTON" at 58.4,46.8 h0.82
  text "2" at 47.774,46.708 h0.82
  text "3" at 47.774,44.656 h0.82
  text "GND" at 51.9,44.6 h0.82
  text "J44" at -20.2,44.189 h2.05
  text "J42" at 28.3,44.189 h2.05
  text "VCC_MCA" at 21.1,41.7 h0.82
  text "15.4_SPI_FRM" at -27.351,41.623 h0.82
  text "2" at -24.326,41.623 h0.82
  text "1" at -21.305,41.623 h0.82
  text "2" at 24.174,41.623 h0.82
  text "1" at 27.295,41.623 h0.82
  text "PCM_MCLK" at -12.7,41.6 h0.82
  text "VCC_MCA" at 34.6,41.6 h0.82
  text "MCA_IO12" at 21.1,39.7 h0.82
  text "MCA_CLKOUT32K" at 39.5,39.6 h0.82
  text "15.4_SPI_INT" at -27.351,39.571 h0.82
  text "4" at -24.326,39.571 h0.82
  text "3" at -21.305,39.571 h0.82
  text "PCM_CLK" at -13.518,39.571 h0.82
  text "4" at 24.174,39.571 h0.82
  text "3" at 27.295,39.571 h0.82
  text "J46" at -57.153,37.772 h2.05
  text "MCA_IO13" at 21.1,37.6 h0.82
  text "MCA_UART_TX" at 37.9,37.6 h0.82
  text "15.4_SPI_RXD" at -27.351,37.518 h0.82
  text "6" at -24.326,37.518 h0.82
  text "5" at -21.305,37.518 h0.82
  text "PCM_IN" at -14.475,37.518 h0.82
  text "6" at 24.174,37.518 h0.82
  text "5" at 27.295,37.518 h0.82
  text "MCA_IO14" at 21.1,35.6 h0.82
  text "MCA_UART_RX" at 37.9,35.6 h0.82
  text "15.4_SPI_TXD" at -27.351,35.466 h0.82
  text "8" at -24.326,35.466 h0.82
  text "7" at -21.305,35.466 h0.82
  text "PCM_OUT" at -13.518,35.466 h0.82
  text "8" at 24.174,35.466 h0.82
  text "7" at 27.295,35.466 h0.82
  text "2" at -61.279,35.307 h0.82
  text "1" at -58.258,35.307 h0.82
  text "LINE1_IN_L" at -64.43,35.207 h0.82
  text "LINE1_IN_R" at -48.524,35.207 h0.82
  text "MCA_IO15" at 21.1,33.6 h0.82
  text "MCA_UART_CTS" at 38.7,33.6 h0.82
  text "15.4_SPI_CLK" at -27.351,33.413 h0.82
  text "10" at -24.326,33.413 h0.82
  text "9" at -21.305,33.413 h0.82
  text "PCM_SYNC" at -12.697,33.413 h0.82
  text "10" at 24.174,33.413 h0.82
  text "9" at 27.295,33.413 h0.82
  text "4" at -61.279,33.254 h0.82
  text "3" at -58.258,33.254 h0.82
  text "LINE2_IN_L" at -64.43,33.154 h0.82
  text "LINE2_IN_R" at -48.387,33.154 h0.82
  text "MCA_IO16" at 21.1,31.6 h0.82
  text "MCA_UART_RTS" at 38.7,31.6 h0.82
  text "12" at 24.174,31.361 h0.82
  text "11" at 27.295,31.361 h0.82
  text "6" at -61.279,31.202 h0.82
  text "5" at -58.258,31.202 h0.82
  text "LINE_OUT_L" at -64.43,31.102 h0.82
  text "LINE_OUT_R" at -48.25,31.102 h0.82
  text "MCA_IO9" at 34.5,29.6 h0.82
  text "MCA_IO17" at 21.1,29.5 h0.82
  text "14" at 24.174,29.308 h0.82
  text "13" at 27.295,29.308 h0.82
  text "8" at -61.279,29.149 h0.82
  text "7" at -58.258,29.149 h0.82
  text "SPKL_N" at -64.43,29.049 h0.82
  text "SPKL_P" at -51.396,29.049 h0.82
  text "MCA_IO18" at 21.1,27.5 h0.82
  text "MCA_IO10" at 35.1,27.5 h0.82
  text "16" at 24.174,27.256 h0.82
  text "15" at 27.295,27.256 h0.82
  text "J46" at -79.5,27.234 h2 r270
  text "10" at -61.279,27.097 h0.82
  text "9" at -58.258,27.097 h0.82
  text "SPKR_N" at -64.43,26.997 h0.82
  text "SPKR_P" at -51.396,26.997 h0.82
  text "MCA_IO11" at 34.9,25.5 h0.82
  text "MCA_VREF_OUT" at 21.1,25.4 h0.82
  text "18" at 24.174,25.203 h0.82
  text "17" at 27.295,25.203 h0.82
  text "GND" at 21.2,23.3 h0.82
  text "GND" at 31.5,23.3 h0.82
  text "20" at 24.174,23.15 h0.82
  text "19" at 27.295,23.15 h0.82
  text "J47" at -36.032,21.546 h2.05
  text "LDO2" at -31.8,19.8 h0.82
  text "2" at -40.047,19.023 h0.82
  text "1" at -37.026,19.023 h0.82
  text "LDO3" at -43.323,18.946 h0.82
  text "4" at -40.047,16.971 h0.82
  text "3" at -37.026,16.971 h0.82
  text "NC" at -43.323,16.946 h0.82
  text "3V3" at -32.611,16.946 h0.82
  text "VCC_MCA" at -43.323,14.946 h0.82
  text "6" at -40.047,14.918 h0.82
  text "5" at -37.026,14.918 h0.82
  text "1V8" at -32.748,14.846 h0.82
  text "J47" at -79.5,14.234 h2 r270
  text "SWIN" at -31.927,12.946 h0.82
  text "8" at -40.047,12.866 h0.82
  text "7" at -37.026,12.866 h0.82
  text "SWOUT" at -43.323,12.846 h0.82
  text "GND" at -43.323,10.846 h0.82
  text "SW_EN" at -30.97,10.846 h0.82
  text "10" at -40.047,10.813 h0.82
  text "9" at -37.026,10.813 h0.82
  text "J48" at -36.032,6.946 h2.05
  text "ADC_IN0" at -29.37,4.446 h0.82
  text "2" at -40.047,4.423 h0.82
  text "1" at -37.026,4.423 h0.82
  text "CLKIN1" at -43.423,4.209 h0.82
  text "4" at -40.047,2.371 h0.82
  text "3" at -37.026,2.371 h0.82
  text "ADC_IN1" at -29.643,2.346 h0.82
  text "CLKIN2" at -43.423,2.209 h0.82
  text "SW3 (BOOT)" at 70.4,1.5 h2.55
  text "J48" at -79.5,0.534 h2 r270
  text "6" at -40.047,0.318 h0.82
  text "5" at -37.026,0.318 h0.82
  text "ADC_IN2" at -29.37,0.246 h0.82
  text "TAMPER0" at -43.423,0.209 h0.82
  text "SW3.3" at 76.724,-1.58 h2.55
  text "SW3.2" at 83.093,-1.58 h2.55
  text "SW3.1" at 89.462,-1.58 h2.55
  text "Description" at 47.2,-1.6 h2.55
  text "BOOT_MODE[3..0]" at 64,-1.6 h2.55
  text "SW3.4" at 70.4,-1.6 h2.55
  text "ADC_IN3" at -29.37,-1.654 h0.82
  text "8" at -40.047,-1.734 h0.82
  text "7" at -37.026,-1.734 h0.82
  text "TAMPER1" at -43.423,-1.891 h0.82
  text "MIKROBUS_PWM" at -43.423,-3.617 h0.82
  text "10" at -40.047,-3.787 h0.82
  text "9" at -37.026,-3.787 h0.82
  text "MIKROBUS_ADC" at -25.2,-3.8 h0.82
  text "USDHC1 8-bit eMMC 5.1" at 47.3,-4.1 h2.55
  text "x010" at 58.231,-4.1 h2.5
  text "X" at 68.2,-4.1 h2.5
  text "OFF" at 75.6,-4.1 h2.55
  text "OFF" at 81.7,-4.1 h2.55
  text "OFF" at 88.3,-4.1 h2.55
  text "Infinite Loop" at 47.231,-6.6 h2.55
  text "x110" at 58.231,-6.6 h2.5
  text "X" at 68.2,-6.6 h2.5
  text "ON" at 75.6,-6.6 h2.55
  text "OFF" at 81.7,-6.6 h2.55
  text "OFF" at 88.3,-6.6 h2.55
  text "J65" at -36.032,-7.654 h2.05
  text "From internal fuses" at 47.2,-9.2 h2.55
  text "x000" at 58.231,-9.2 h2.5
  text "X" at 68.2,-9.2 h2.5
  text "OFF" at 75.6,-9.2 h2.55
  text "ON" at 81.7,-9.2 h2.55
  text "OFF" at 88.3,-9.2 h2.55
  text "2" at -40.047,-10.177 h0.82
  text "1" at -37.026,-10.177 h0.82
  text "1V8" at -32.587,-10.154 h0.82
  text "3V3" at -43.423,-10.391 h0.82
  text "CS" at 106.7,-10.726 h1 r270
  text "AN" at 111.8,-10.726 h1 r270
  text "GND" at 94,-11.725 h1 r270
  text "SCK" at 104.2,-11.725 h1 r270
  text "RST" at 109.3,-11.725 h1 r270
  text "FlexSPI Serial NOR" at 47.2,-11.8 h2.55
  text "x100" at 58.231,-11.8 h2.5
  text "X" at 68.2,-11.8 h2.5
  text "ON" at 75.6,-11.8 h2.55
  text "ON" at 81.7,-11.8 h2.55
  text "OFF" at 88.3,-11.8 h2.55
  text "4" at -40.047,-12.229 h0.82
  text "3" at -37.026,-12.229 h0.82
  text "GPIO4_IO22" at -43.423,-12.254 h0.82
  text "GPIO3_IO26" at -26.978,-12.254 h0.82
  text "MOSI" at 99.1,-12.392 h1 r270
  text "MISO" at 101.7,-12.558 h1 r270
  text "+3V3" at 96.6,-12.725 h1 r270
  text "J65" at -79.5,-13.086 h2 r270
  text "GPIO4_IO25" at -43.423,-14.254 h0.82
  text "6" at -40.047,-14.282 h0.82
  text "5" at -37.026,-14.282 h0.82
  text "GPIO3_IO27" at -26.978,-14.354 h0.82
  text "USDHC2 4-bit SD3.0" at 47.2,-14.4 h2.55
  text "x011" at 58.231,-14.4 h2.5
  text "X" at 68.2,-14.4 h2.5
  text "OFF" at 75.6,-14.4 h2.55
  text "OFF" at 81.7,-14.4 h2.55
  text "ON" at 88.3,-14.4 h2.55
  text "GPIO4_IO16" at -27.115,-16.254 h0.82
  text "8" at -40.047,-16.334 h0.82
  text "7" at -37.026,-16.334 h0.82
  text "GPIO4_IO27" at -43.423,-16.354 h0.82
  text "Test Mode" at 47.2,-16.9 h2.55
  text "x111" at 58.231,-16.9 h2.5
  text "X" at 68.2,-16.9 h2.5
  text "ON" at 75.6,-16.9 h2.55
  text "OFF" at 81.7,-16.9 h2.55
  text "ON" at 88.3,-16.9 h2.55
  text "BUS" at 114.7,-17 h1.5 r270
  text "mikro" at 116.58,-17.11 h1 r270
  text "GND" at -43.423,-18.354 h0.82
  text "10" at -40.047,-18.387 h0.82
  text "9" at -37.026,-18.387 h0.82
  text "GPIO4_IO17" at -27.115,-18.4 h0.82
  text "Serial Downloader" at 47.2,-19.5 h2.55
  text "x001" at 58.231,-19.5 h2.5
  text "X" at 68.2,-19.5 h2.5
  text "OFF" at 75.6,-19.5 h2.55
  text "ON" at 81.7,-19.5 h2.55
  text "ON" at 88.3,-19.5 h2.55
  text "FlexSPI Serial NAND 2K Page" at 47.2,-22 h2.55
  text "x101" at 58.231,-22 h2.5
  text "X" at 68.2,-22 h2.5
  text "ON" at 75.6,-22 h2.55
  text "ON" at 81.7,-22 h2.55
  text "ON" at 88.3,-22 h2.55
  text "Leaving SW3.4 open selects the Cortex-A55." at 89.5,-24.4 h1.2
  text "J41" at -57.832,-24.954 h2.05
  text "GND" at 94,-25.8 h1 r270
  text "+5V" at 96.7,-25.8 h1 r270
  text "SDA" at 99.2,-25.8 h1 r270
  text "SCL" at 101.7,-25.8 h1 r270
  text "TX" at 104.2,-25.8 h1 r270
  text "RX" at 106.8,-25.8 h1 r270
  text "INT" at 109.3,-25.8 h1 r270
  text "PWM" at 111.9,-25.8 h1 r270
  text "Closing it selects the Cortex-M33." at 89.5,-26.3 h1.2
  text "1" at -61.226,-27.377 h0.82
  text "2" at -58.147,-27.377 h0.82
  text "3V3_RF" at -64.5,-27.4 h0.82
  text "WLAN_SD3_CLK" at -46.779,-27.4 h0.82
  text "BT_UART1_TX" at -64.5,-29.4 h0.82
  text "WLAN_SD3_CMD" at -46.779,-29.4 h0.82
  text "3" at -61.226,-29.429 h0.82
  text "4" at -58.147,-29.429 h0.82
  text "5" at -61.226,-31.482 h0.82
  text "6" at -58.147,-31.482 h0.82
  text "BT_UART1_RX" at -64.5,-31.5 h0.82
  text "WLAN_SD3_D0" at -47.6,-31.5 h0.82
  text "J41" at -79.5,-32.733 h2 r270
  text "WLAN_SD3_D1" at -47.874,-33.5 h0.82
  text "7" at -61.226,-33.534 h0.82
  text "8" at -58.147,-33.534 h0.82
  text "BT_UART1_CTS" at -64.5,-33.6 h0.82
  text "BT_UART1_RTS" at -64.5,-35.6 h0.82
  text "9" at -61.226,-35.587 h0.82
  text "10" at -58.147,-35.587 h0.82
  text "WLAN_SD3_D2" at -47.6,-35.6 h0.82
  text "11" at -61.226,-37.639 h0.82
  text "12" at -58.147,-37.639 h0.82
  text "GND" at -64.5,-37.7 h0.82
  text "WLAN_SD3_D3" at -47.6,-37.7 h0.82
  text "13" at -61.226,-39.692 h0.82
  text "14" at -58.147,-39.692 h0.82
  text "BT_HOST_WAKE" at -64.5,-39.7 h0.82
  text "GND" at -54.166,-39.7 h0.82
  text "BT_DEV_WAKE" at -64.5,-41.7 h0.82
  text "WL_DEV_WAKE" at -47.6,-41.7 h0.82
  text "15" at -61.226,-41.744 h0.82
  text "16" at -58.147,-41.744 h0.82
  text "17" at -61.226,-43.797 h0.82
  text "18" at -58.147,-43.797 h0.82
  text "WL_HOST_WAKE" at -46.779,-43.817 h0.82
  text "GND" at -64.5,-43.9 h0.82
  text "J66" at -1.6,-44.7 h2.05
  text "GND" at -54.166,-45.8 h0.82
  text "19" at -61.226,-45.85 h0.82
  text "20" at -58.147,-45.85 h0.82
  text "GND" at -64.5,-46 h0.82
  text "I3C2_SCL" at 4.1,-46.7 h0.82
  text "1" at -4.1,-47.2 h0.82
  text "I3C2_SDA" at 4,-49.1 h0.82
  text "2" at -3.926,-49.292 h0.82
  text "3" at -3.926,-51.344 h0.82
  text "GND" at 0.352,-51.417 h0.82
Board Outline:
  lines w0.25: -85.7,-67.8 -85.7,62.2 124.3,62.2 124.3,-67.8 -85.7,-67.8 ; -10.75,-16 ccw(c-9.76,-16.01) -9.771,-17 10,-17 ccw(c10,-16.25) 10.75,-16.25 10.75,16 ccw(c9.75,16) 9.75,17 -9.75,17 ccw(c-9.75,16) -10.75,16 -10.75,-16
